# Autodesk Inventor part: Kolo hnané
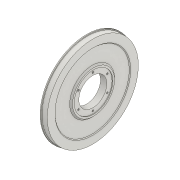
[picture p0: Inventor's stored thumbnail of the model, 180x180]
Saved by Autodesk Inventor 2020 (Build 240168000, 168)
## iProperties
Created: 2025-03
Part Number: Kolo hnané
Material: Ocel
Document SubType Name: Modeling
Designer: doma
Density: 7.85 g/cm^3
Appearance: Ocel
Mass: 5965.76 g
Surface Area: 1268.34 cm^2
Volume: 759.97 cm^3
Author: doma
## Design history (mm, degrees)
sketch "Náčrt1"
  geometry: L1 (-2, 130)-(-2, 132.5); L2 (-2, 132.5)-(-5, 132.5); L3 (-5, 40)-(15, 40); L4 (15, 130)-(-2, 130); L5 (15, 130)-(15, 110); L6 (15, 110)-(11, 110); L7 (11, 110)-(11, 106); L8 (11, 106)-(15, 110); L9 (11, 106)-(11, 64); L10 (11, 64)-(11, 60); L11 (11, 60)-(15, 60); L12 (15, 60)-(11, 64); L13 (15, 60)-(15, 40); L14 (5, 40)-(5, 28.239); L15 (-1, 106)-(-1, 64); L16 (-5, 60)-(-1, 64); L17 (-1, 106)-(-5, 110); L18 (-5, 132.5)-(-5, 110); L19 (-5, 60)-(-5, 40); L20 (-28.012, 0)-(19.413, 0); L21 (15, 55)-(13, 55); L22 (13, 55)-(13, 40); 1 further point
  constraints: 44 end point, 9 perpendicular, 5 vertical, 4 symmetric about line, 3 point on line, 2 horizontal, 1 midpoint
  dimensions: "d0" = 2.5 distance of L1.start L1.end; "d1" = 3 distance of L1.end L2.end; "d2" = 20 distance of L3.start L3.end; "d3" = 20 distance of L4.start L5.end; "d4" = 4 distance of L5.end L6.end; "d5" = 4 distance of L6.end L7.end; "d6" = 4 distance of L9.end L10.end; "d7" = 4 distance of L10.end L11.end; "d8" = 130 distance from line of point (0, 0) L4; "d11" = 60 vertical distance of point (0, 0) L11.end; "d12" = 40 distance from line of point (0, 0) L3; "d26" = 2 distance of L21.start L21.end; "d28" = 55 distance from line of point (0, 0) L21
revolve "Rotace1" sketch "Náčrt1" stored, may be unused: angle "d13" = 120 deg
sketch "Náčrt2"
  geometry: 7 further points
  constraints: 7 other
  dimensions: "d17" = 360 deg dimension on point (0, 0) point (0, 47.5) (derived); "d29" = 47.5 distance of point (0, 47.5) point (0, 0)
hole "Díra1" sketch "Náčrt2" at (0, 47.5), (-41.136, 23.75), (-41.136, -23.75), (0, -47.5), (41.136, -23.75), (41.136, 23.75) diameter "d19" = 4.917; stored, may be unused: countersink angle "d23" = 90 deg, drill point angle "d25" = 118 deg; dims "d20" = 12, "d21" = 14, "d22" = 8, "d24" = 17.1
sketch "Náčrt3"
  geometry: C1 r 91.093 at (0, 0); C2 r 159.828 at (0, 0); 1 further point
  constraints: 2 centre point, 2 coincident
extrude "Vysunutí1" cut sketch "Náčrt3" distance "d30" = 2; taper "d31" = 0 deg
node "Těleso1"
